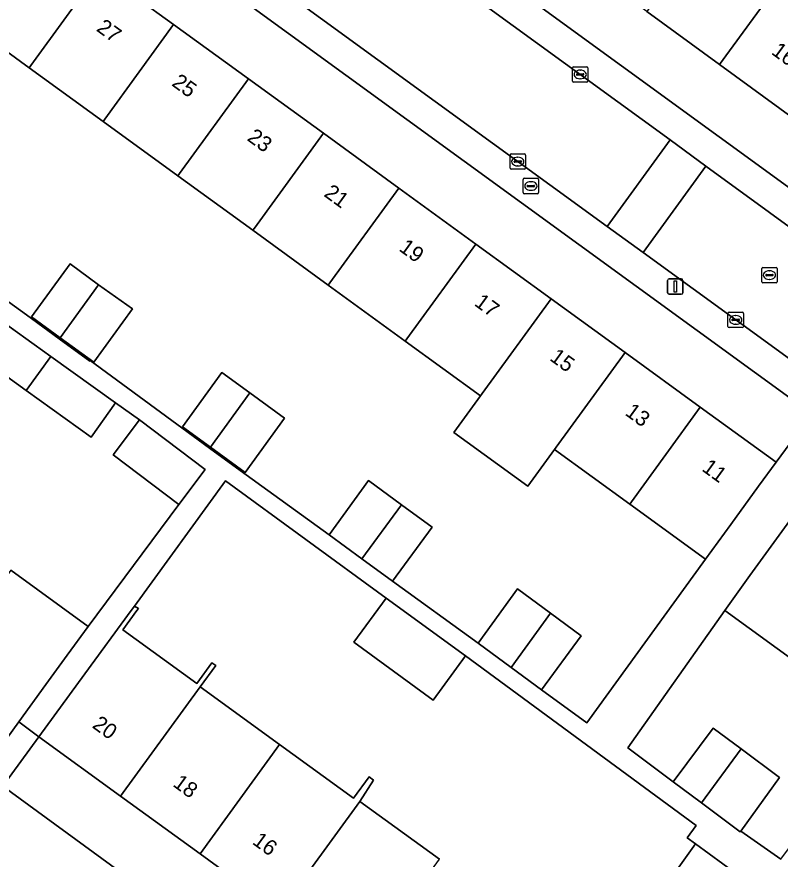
# Model space of a CAD drawing. Extents: x 159674 to 160531, y 382172 to 382904.
# Drawn here: x 160126.2 to 160175.7, y 382483.9 to 382538.5 of the extents above; entities that cross this region are included whole.
import ezdxf

# ---------------------------------------------------------------- set-up
doc = ezdxf.new("R2010")
doc.units = 0
for name, color, linetype in [('IMGEO_Brandkraan', 7, 'Continuous'), ('IMGEO_Erf', 7, 'Continuous'), ('IMGEO_Kolk', 7, 'Continuous'), ('IMGEO_Lichtmast', 7, 'Continuous'), ('IMGEO_Pand', 7, 'Continuous'), ('IMGEO_Pand_nummerreeks', 7, 'Continuous'), ('IMGEO_Rijbaan_lokaal_open', 7, 'Continuous'), ('IMGEO_Rioolput', 7, 'Continuous'), ('IMGEO_Voetpad_open', 7, 'Continuous')]:
    doc.layers.add(name, color=color, linetype=linetype)

msp = doc.modelspace()

# ---------------------------------------------------------------- linework, layer by layer
at = {"layer": 'IMGEO_Brandkraan'}
for p, q in [((160159.064, 382527.12), (160159.064, 382527.972)), ((160159.139, 382528.046), (160159.991, 382528.046)), ((160159.552, 382527.826), (160159.577, 382527.826)), ((160160.065, 382527.972), (160160.065, 382527.12)), ((160159.323, 382527.54), (160159.323, 382527.552)), ((160159.761, 382527.503), (160159.363, 382527.503)), ((160159.366, 382527.589), (160159.764, 382527.589)), ((160159.575, 382527.266), (160159.55, 382527.266)), ((160159.807, 382527.552), (160159.807, 382527.54)), ((160159.991, 382527.046), (160159.139, 382527.046))]:
    msp.add_line(p, q, dxfattribs=at)
for points in [[(160159.064, 382527.12), (160159.064, 382527.972)], [(160159.139, 382528.046), (160159.991, 382528.046)], [(160160.065, 382527.972), (160160.065, 382527.12)], [(160159.991, 382527.046), (160159.139, 382527.046)]]:
    msp.add_lwpolyline(points, dxfattribs=at)
for centre, radius, start, end in [((160159.141, 382527.97), 0.0765, 91.552, 178.448), ((160159.141, 382527.97), 0.0765, 91.552, 178.448), ((160159.989, 382527.97), 0.0765, 1.552, 88.448), ((160159.989, 382527.97), 0.0765, 1.552, 88.448), ((160159.363, 382527.549), 0.0403, 85.8775, 175.7526), ((160159.36, 382527.539), 0.0366, 178.938, 274.7102), ((160159.764, 382527.546), 0.043, 264.8664, 352.4533), ((160159.768, 382527.551), 0.0386, 1.7309, 96.639), ((160159.141, 382527.122), 0.0765, 181.552, 268.448), ((160159.141, 382527.122), 0.0765, 181.552, 268.448), ((160159.989, 382527.122), 0.0765, 271.552, 358.448), ((160159.989, 382527.122), 0.0765, 271.552, 358.448)]:
    msp.add_arc(centre, radius, start, end, dxfattribs=at)
for centre, major_axis, ratio, start_param, end_param in [((160159.551, 382527.546), (-0.387, 0.002), 0.722429, 4.712389, 7.853982), ((160159.576, 382527.546), (-0.39, 0.002), 0.717154, 1.570796, 4.712389)]:
    msp.add_ellipse(centre, major_axis=major_axis, ratio=ratio, start_param=start_param, end_param=end_param, dxfattribs=at)
at = {"layer": 'IMGEO_Erf'}
for points in [[(160127.897, 382562.669), (160184.209, 382521.695), (160184.808, 382522.535), (160186.417, 382524.795), (160181.637, 382528.275), (160176.758, 382531.828), (160171.799, 382535.439), (160167.082, 382538.873), (160162.337, 382542.328), (160157.384, 382545.934)], [(160117.459, 382553.168), (160116.806, 382552.256), (160121.807, 382548.622), (160126.656, 382545.098), (160131.584, 382541.517), (160136.387, 382538.026), (160141.237, 382534.502), (160146.105, 382530.965), (160150.991, 382527.414), (160155.991, 382523.78), (160160.872, 382520.234), (160165.672, 382516.745), (160170.553, 382513.198), (160175.469, 382509.626), (160177.234, 382512.001), (160177.794, 382512.755), (160121.273, 382553.859)], [(160121.293, 382523.187), (160126.833, 382519.19), (160128.969, 382517.622), (160130.945, 382516.172), (160130.979, 382516.218), (160136.587, 382512.101), (160138.724, 382510.532), (160140.699, 382509.083), (160146.468, 382504.92), (160149.018, 382508.437), (160151.159, 382506.866), (160153.151, 382505.404), (160150.58, 382501.902), (160156.148, 382497.884), (160158.698, 382501.401), (160160.839, 382499.83), (160162.831, 382498.368), (160160.26, 382494.866), (160163.181, 382492.722), (160170.895, 382503.333), (160165.979, 382506.906), (160161.098, 382510.453), (160159.362, 382508.064), (160154.564, 382511.551), (160156.297, 382513.941), (160151.417, 382517.488), (160146.418, 382521.12), (160141.531, 382524.672), (160136.663, 382528.21), (160131.814, 382531.734), (160127.01, 382535.224), (160122.082, 382538.806)], [(160125.823, 382502.62), (160130.845, 382498.975), (160136.723, 382506.88), (160132.467, 382510.102), (160134.182, 382512.366), (160132.611, 382513.47), (160131.029, 382511.262), (160126.818, 382514.281), (160123.027, 382517)], [(160167.97, 382481.681), (160170.234, 382484.868), (160169.698, 382485.261), (160170.274, 382486.048), (160155.319, 382497.055), (160153.231, 382494.194), (160148.078, 382497.954), (160150.166, 382500.815), (160139.754, 382508.413), (160133.844, 382500.294), (160134.105, 382500.145), (160133.999, 382500), (160133.09, 382498.758), (160137.889, 382495.27), (160138.869, 382496.618), (160139.115, 382496.439), (160138.113, 382495.063), (160143.265, 382491.318), (160148.063, 382487.832), (160149.063, 382489.208), (160149.354, 382488.996), (160148.464, 382487.621), (160153.625, 382483.87)], [(160182.094, 382492.77), (160177.116, 382496.389), (160172.149, 382500), (160165.851, 382491.086), (160168.791, 382488.896), (160171.386, 382492.38), (160173.197, 382491.031), (160175.695, 382489.17), (160173.177, 382485.697), (160175.768, 382483.874), (160179.323, 382488.647), (160182.164, 382486.531), (160181.035, 382485.016), (160182.848, 382483.665), (160184.767, 382482.236), (160182.34, 382478.979), (160182.963, 382478.515), (160185.543, 382476.768), (160187.968, 382480.105), (160192.854, 382476.554), (160193.609, 382475.995), (160197.153, 382480.914)]]:
    msp.add_lwpolyline(points, dxfattribs=at)
for points in [[(160129.028, 382517.703), (160127.167, 382519.053), (160129.666, 382522.499), (160131.523, 382521.136), (160133.71, 382519.567), (160131.211, 382516.121)], [(160141.333, 382514.123), (160143.589, 382512.486), (160141.037, 382508.966), (160138.776, 382510.604), (160136.952, 382511.927), (160139.505, 382515.448)], [(160143.26, 382480.459), (160138.099, 382484.21), (160132.938, 382487.961), (160127.653, 382491.801), (160125.316, 382488.609), (160161.358, 382462.265), (160161.521, 382462.147), (160163.916, 382465.448), (160163.756, 382465.564), (160158.743, 382469.207), (160153.582, 382472.958), (160148.42, 382476.709)]]:
    msp.add_lwpolyline(points, close=True, dxfattribs=at)
at = {"layer": 'IMGEO_Kolk'}
for p, q in [((160162.26, 382534.357), (160162.26, 382535.209)), ((160162.335, 382535.283), (160163.187, 382535.283)), ((160162.748, 382535.063), (160162.773, 382535.063)), ((160163.261, 382535.209), (160163.261, 382534.357)), ((160162.519, 382534.777), (160162.519, 382534.789)), ((160162.957, 382534.74), (160162.559, 382534.74)), ((160162.562, 382534.826), (160162.96, 382534.826)), ((160162.771, 382534.503), (160162.746, 382534.503)), ((160163.003, 382534.789), (160163.003, 382534.777)), ((160163.187, 382534.283), (160162.335, 382534.283)), ((160158.211, 382528.704), (160158.211, 382529.556)), ((160158.286, 382529.63), (160159.138, 382529.63)), ((160158.699, 382529.41), (160158.724, 382529.41)), ((160159.212, 382529.556), (160159.212, 382528.704)), ((160158.47, 382529.124), (160158.47, 382529.136)), ((160158.908, 382529.087), (160158.51, 382529.087)), ((160158.513, 382529.173), (160158.911, 382529.173)), ((160158.722, 382528.85), (160158.697, 382528.85)), ((160158.954, 382529.136), (160158.954, 382529.124)), ((160159.138, 382528.63), (160158.286, 382528.63)), ((160172.347, 382518.432), (160172.347, 382519.284)), ((160172.422, 382519.358), (160173.274, 382519.358)), ((160172.835, 382519.138), (160172.86, 382519.138)), ((160173.348, 382519.284), (160173.348, 382518.432)), ((160172.606, 382518.852), (160172.606, 382518.864)), ((160173.044, 382518.815), (160172.646, 382518.815)), ((160172.649, 382518.901), (160173.047, 382518.901)), ((160172.858, 382518.578), (160172.833, 382518.578)), ((160173.09, 382518.864), (160173.09, 382518.852)), ((160173.274, 382518.358), (160172.422, 382518.358))]:
    msp.add_line(p, q, dxfattribs=at)
for points in [[(160162.26, 382534.357), (160162.26, 382535.209)], [(160162.335, 382535.283), (160163.187, 382535.283)], [(160163.261, 382535.209), (160163.261, 382534.357)], [(160163.187, 382534.283), (160162.335, 382534.283)], [(160158.211, 382528.704), (160158.211, 382529.556)], [(160158.286, 382529.63), (160159.138, 382529.63)], [(160159.212, 382529.556), (160159.212, 382528.704)], [(160159.138, 382528.63), (160158.286, 382528.63)], [(160172.347, 382518.432), (160172.347, 382519.284)], [(160172.422, 382519.358), (160173.274, 382519.358)], [(160173.348, 382519.284), (160173.348, 382518.432)], [(160173.274, 382518.358), (160172.422, 382518.358)]]:
    msp.add_lwpolyline(points, dxfattribs=at)
for centre, radius, start, end in [((160162.337, 382535.207), 0.0765, 91.552, 178.448), ((160162.337, 382535.207), 0.0765, 91.552, 178.448), ((160163.185, 382535.207), 0.0765, 1.552, 88.448), ((160163.185, 382535.207), 0.0765, 1.552, 88.448), ((160162.337, 382534.359), 0.0765, 181.552, 268.448), ((160162.337, 382534.359), 0.0765, 181.552, 268.448), ((160162.559, 382534.786), 0.0403, 85.8775, 175.7526), ((160162.556, 382534.776), 0.0366, 178.938, 274.7102), ((160162.96, 382534.783), 0.043, 264.8664, 352.4533), ((160162.964, 382534.788), 0.0386, 1.7309, 96.639), ((160163.185, 382534.359), 0.0765, 271.552, 358.448), ((160163.185, 382534.359), 0.0765, 271.552, 358.448), ((160158.288, 382529.554), 0.0765, 91.552, 178.448), ((160158.288, 382529.554), 0.0765, 91.552, 178.448), ((160159.136, 382529.554), 0.0765, 1.552, 88.448), ((160159.136, 382529.554), 0.0765, 1.552, 88.448), ((160158.51, 382529.133), 0.0403, 85.8775, 175.7526), ((160158.507, 382529.123), 0.0366, 178.938, 274.7102), ((160158.911, 382529.13), 0.043, 264.8664, 352.4533), ((160158.915, 382529.135), 0.0386, 1.7309, 96.639), ((160158.288, 382528.706), 0.0765, 181.552, 268.448), ((160158.288, 382528.706), 0.0765, 181.552, 268.448), ((160159.136, 382528.706), 0.0765, 271.552, 358.448), ((160159.136, 382528.706), 0.0765, 271.552, 358.448), ((160172.424, 382519.282), 0.0765, 91.552, 178.448), ((160172.424, 382519.282), 0.0765, 91.552, 178.448), ((160173.272, 382519.282), 0.0765, 1.552, 88.448), ((160173.272, 382519.282), 0.0765, 1.552, 88.448), ((160172.646, 382518.861), 0.0403, 85.8775, 175.7526), ((160172.643, 382518.851), 0.0366, 178.938, 274.7102), ((160173.047, 382518.858), 0.043, 264.8664, 352.4533), ((160173.051, 382518.863), 0.0386, 1.7309, 96.639), ((160172.424, 382518.434), 0.0765, 181.552, 268.448), ((160172.424, 382518.434), 0.0765, 181.552, 268.448), ((160173.272, 382518.434), 0.0765, 271.552, 358.448), ((160173.272, 382518.434), 0.0765, 271.552, 358.448)]:
    msp.add_arc(centre, radius, start, end, dxfattribs=at)
for centre, major_axis, ratio, start_param, end_param in [((160162.747, 382534.783), (-0.387, 0.002), 0.722429, 4.712389, 7.853982), ((160162.772, 382534.783), (-0.39, 0.002), 0.717154, 1.570796, 4.712389), ((160158.698, 382529.13), (-0.387, 0.002), 0.722429, 4.712389, 7.853982), ((160158.723, 382529.13), (-0.39, 0.002), 0.717154, 1.570796, 4.712389), ((160172.834, 382518.858), (-0.387, 0.002), 0.722429, 4.712389, 7.853982), ((160172.859, 382518.858), (-0.39, 0.002), 0.717154, 1.570796, 4.712389)]:
    msp.add_ellipse(centre, major_axis=major_axis, ratio=ratio, start_param=start_param, end_param=end_param, dxfattribs=at)
at = {"layer": 'IMGEO_Lichtmast'}
for p, q in [((160168.429, 382520.624), (160168.429, 382521.424)), ((160168.429, 382521.424), (160168.429, 382520.624)), ((160168.529, 382521.524), (160169.319, 382521.524)), ((160169.319, 382521.524), (160168.529, 382521.524)), ((160169.419, 382521.424), (160169.419, 382520.624)), ((160169.419, 382520.624), (160169.419, 382521.424)), ((160169.319, 382520.524), (160168.529, 382520.524)), ((160168.529, 382520.524), (160169.319, 382520.524))]:
    msp.add_line(p, q, dxfattribs=at)
msp.add_lwpolyline([(160168.849, 382521.399), (160168.999, 382521.399), (160168.999, 382520.649), (160168.849, 382520.649), (160168.849, 382521.399)], dxfattribs=at)
for centre, start, end in [((160168.529, 382521.424), 90, 180), ((160168.529, 382521.424), 90, 180), ((160169.319, 382521.424), 0, 90), ((160169.319, 382521.424), 360, 90), ((160168.529, 382520.624), 180, 270), ((160168.529, 382520.624), 180, 270), ((160169.319, 382520.624), 270, 0), ((160169.319, 382520.624), 270, 0)]:
    msp.add_arc(centre, 0.1, start, end, dxfattribs=at)
at = {"layer": 'IMGEO_Pand'}
for points in [[(160122.082, 382538.806), (160127.01, 382535.224), (160127.119, 382535.372), (160131.584, 382541.517), (160126.656, 382545.098), (160122.19, 382538.954)], [(160167.082, 382538.873), (160171.799, 382535.439), (160176.396, 382541.751), (160171.679, 382545.186)], [(160131.584, 382541.517), (160127.119, 382535.372), (160127.01, 382535.224), (160131.814, 382531.734), (160131.922, 382531.882), (160136.387, 382538.026)], [(160181.355, 382538.141), (160176.396, 382541.751), (160171.799, 382535.439), (160176.758, 382531.828)], [(160136.663, 382528.21), (160136.771, 382528.357), (160141.237, 382534.502), (160136.387, 382538.026), (160131.922, 382531.882), (160131.814, 382531.734)], [(160136.663, 382528.21), (160141.531, 382524.672), (160141.639, 382524.819), (160146.105, 382530.965), (160141.237, 382534.502), (160136.771, 382528.357)], [(160146.418, 382521.12), (160146.525, 382521.268), (160150.991, 382527.414), (160146.105, 382530.965), (160141.639, 382524.819), (160141.531, 382524.672)], [(160146.418, 382521.12), (160151.417, 382517.488), (160151.525, 382517.634), (160155.991, 382523.78), (160150.991, 382527.414), (160146.525, 382521.268)], [(160151.417, 382517.488), (160156.297, 382513.941), (160156.406, 382514.087), (160160.872, 382520.234), (160155.991, 382523.78), (160151.525, 382517.634)], [(160131.523, 382521.136), (160129.666, 382522.499), (160127.167, 382519.053), (160129.028, 382517.703)], [(160131.523, 382521.136), (160129.028, 382517.703), (160131.211, 382516.121), (160133.71, 382519.567)], [(160165.672, 382516.745), (160160.872, 382520.234), (160156.406, 382514.087), (160156.297, 382513.941), (160154.564, 382511.551), (160159.362, 382508.064), (160161.098, 382510.453), (160161.205, 382510.598)], [(160126.818, 382514.281), (160128.414, 382516.479), (160124.609, 382519.207), (160123.027, 382517)], [(160126.818, 382514.281), (160131.029, 382511.262), (160132.611, 382513.47), (160128.414, 382516.479)], [(160170.553, 382513.198), (160165.672, 382516.745), (160161.205, 382510.598), (160161.098, 382510.453), (160165.979, 382506.906), (160166.086, 382507.051)], [(160141.333, 382514.123), (160139.505, 382515.448), (160136.952, 382511.927), (160138.776, 382510.604)], [(160141.333, 382514.123), (160138.776, 382510.604), (160141.037, 382508.966), (160143.589, 382512.486)], [(160170.553, 382513.198), (160166.086, 382507.051), (160165.979, 382506.906), (160170.895, 382503.333), (160172.53, 382505.582), (160174.336, 382508.068), (160175.469, 382509.626)], [(160134.182, 382512.366), (160132.467, 382510.102), (160136.723, 382506.88), (160138.437, 382509.144)], [(160148.606, 382503.351), (160151.159, 382506.866), (160149.018, 382508.437), (160146.468, 382504.92)], [(160148.606, 382503.351), (160150.58, 382501.902), (160153.151, 382505.404), (160151.159, 382506.866)], [(160177.116, 382496.389), (160179.757, 382500), (160181.704, 382502.662), (160176.698, 382506.323), (160173.759, 382502.279), (160172.149, 382500)], [(160129.485, 382497.104), (160130.845, 382498.975), (160125.823, 382502.62), (160124.463, 382500.746), (160123.92, 382500), (160120.154, 382494.811), (160125.171, 382491.169), (160126.342, 382492.78), (160128.102, 382495.201)], [(160160.839, 382499.83), (160158.698, 382501.401), (160156.148, 382497.884), (160158.285, 382496.316)], [(160150.166, 382500.815), (160148.078, 382497.954), (160153.231, 382494.194), (160155.319, 382497.055)], [(160138.113, 382495.063), (160139.115, 382496.439), (160138.869, 382496.618), (160137.889, 382495.27), (160133.09, 382498.758), (160133.999, 382500), (160134.105, 382500.145), (160133.844, 382500.294), (160133.63, 382500), (160130.637, 382495.894), (160127.653, 382491.801), (160132.938, 382487.961)], [(160160.839, 382499.83), (160158.285, 382496.316), (160160.26, 382494.866), (160162.831, 382498.368)], [(160143.265, 382491.318), (160138.113, 382495.063), (160132.938, 382487.961), (160138.099, 382484.21)], [(160173.197, 382491.031), (160171.386, 382492.38), (160168.791, 382488.896), (160170.633, 382487.524)], [(160138.099, 382484.21), (160143.26, 382480.459), (160148.464, 382487.621), (160149.354, 382488.996), (160149.063, 382489.208), (160148.063, 382487.832), (160143.265, 382491.318)], [(160175.695, 382489.17), (160173.197, 382491.031), (160170.633, 382487.524), (160173.145, 382485.653), (160173.177, 382485.697)], [(160148.42, 382476.709), (160153.625, 382483.87), (160148.464, 382487.621), (160143.26, 382480.459)], [(160170.234, 382484.868), (160167.97, 382481.681), (160172.364, 382478.461), (160172.878, 382479.162), (160174.675, 382481.615)]]:
    msp.add_lwpolyline(points, close=True, dxfattribs=at)
at = {"layer": 'IMGEO_Rijbaan_lokaal_open'}
for points in [[(160164.514, 382524.914), (160168.596, 382530.532), (160153.206, 382541.739), (160123.485, 382563.377), (160120.554, 382565.511), (160112.814, 382571.146), (160108.691, 382565.482)], [(160164.514, 382524.914), (160166.836, 382523.227), (160170.916, 382528.842), (160168.596, 382530.532)]]:
    msp.add_lwpolyline(points, close=True, dxfattribs=at)
for points in [[(160170.916, 382528.842), (160166.836, 382523.227), (160198.798, 382500), (160204.282, 382495.961)], [(160207.614, 382502.119), (160170.916, 382528.842)]]:
    msp.add_lwpolyline(points, dxfattribs=at)
at = {"layer": 'IMGEO_Rioolput'}
for p, q in [((160174.537, 382521.339), (160174.537, 382522.191)), ((160174.612, 382522.265), (160175.464, 382522.265)), ((160174.796, 382521.759), (160174.796, 382521.771)), ((160174.839, 382521.808), (160175.237, 382521.808)), ((160175.025, 382522.045), (160175.05, 382522.045)), ((160175.28, 382521.771), (160175.28, 382521.759)), ((160175.538, 382522.191), (160175.538, 382521.339)), ((160175.464, 382521.265), (160174.612, 382521.265)), ((160175.234, 382521.722), (160174.836, 382521.722)), ((160175.048, 382521.485), (160175.023, 382521.485))]:
    msp.add_line(p, q, dxfattribs=at)
for points in [[(160174.537, 382521.339), (160174.537, 382522.191)], [(160174.612, 382522.265), (160175.464, 382522.265)], [(160175.538, 382522.191), (160175.538, 382521.339)], [(160175.464, 382521.265), (160174.612, 382521.265)]]:
    msp.add_lwpolyline(points, dxfattribs=at)
for centre, radius, start, end in [((160174.614, 382522.189), 0.0765, 91.552, 178.448), ((160174.614, 382522.189), 0.0765, 91.552, 178.448), ((160174.836, 382521.768), 0.0403, 85.8775, 175.7526), ((160174.833, 382521.758), 0.0366, 178.938, 274.7102), ((160175.237, 382521.765), 0.043, 264.8664, 352.4533), ((160175.241, 382521.77), 0.0386, 1.7309, 96.639), ((160175.462, 382522.189), 0.0765, 1.552, 88.448), ((160175.462, 382522.189), 0.0765, 1.552, 88.448), ((160174.614, 382521.341), 0.0765, 181.552, 268.448), ((160174.614, 382521.341), 0.0765, 181.552, 268.448), ((160175.462, 382521.341), 0.0765, 271.552, 358.448), ((160175.462, 382521.341), 0.0765, 271.552, 358.448)]:
    msp.add_arc(centre, radius, start, end, dxfattribs=at)
for centre, major_axis, ratio, start_param, end_param in [((160175.024, 382521.765), (-0.387, 0.002), 0.722429, 4.712389, 7.853982), ((160175.049, 382521.765), (-0.39, 0.002), 0.717154, 1.570796, 4.712389)]:
    msp.add_ellipse(centre, major_axis=major_axis, ratio=ratio, start_param=start_param, end_param=end_param, dxfattribs=at)
at = {"layer": 'IMGEO_Voetpad_open'}
for points in [[(160103.182, 382578.158), (160110.485, 382572.841), (160112.814, 382571.146), (160120.554, 382565.511), (160121.166, 382566.352), (160124.097, 382564.218), (160123.485, 382563.377), (160153.206, 382541.739), (160168.596, 382530.532), (160170.916, 382528.842), (160207.614, 382502.119)], [(160166.836, 382523.227), (160164.514, 382524.914), (160108.691, 382565.482), (160106.361, 382567.175), (160098.735, 382572.717)], [(160210.164, 382504.096), (160187.205, 382520.79), (160184.808, 382522.535), (160184.209, 382521.695), (160127.897, 382562.669)], [(160121.273, 382553.859), (160177.794, 382512.755), (160177.234, 382512.001), (160179.581, 382510.186), (160193.511, 382500), (160201.923, 382493.849)], [(160177.234, 382512.001), (160175.469, 382509.626), (160174.336, 382508.068), (160172.53, 382505.582), (160170.895, 382503.333), (160163.181, 382492.722), (160160.26, 382494.866), (160158.285, 382496.316), (160156.148, 382497.884), (160150.58, 382501.902), (160148.606, 382503.351), (160146.468, 382504.92), (160140.699, 382509.083), (160138.724, 382510.532), (160136.587, 382512.101), (160130.979, 382516.218), (160130.945, 382516.172), (160128.969, 382517.622), (160126.833, 382519.19), (160121.293, 382523.187)], [(160204.282, 382495.961), (160198.798, 382500), (160166.836, 382523.227)], [(160124.609, 382519.207), (160128.414, 382516.479), (160132.611, 382513.47), (160134.182, 382512.366), (160138.437, 382509.144), (160136.723, 382506.88), (160130.845, 382498.975), (160129.485, 382497.104), (160128.102, 382495.201), (160126.342, 382492.78), (160127.653, 382491.801), (160130.637, 382495.894), (160133.63, 382500), (160133.844, 382500.294), (160139.754, 382508.413), (160150.166, 382500.815), (160155.319, 382497.055), (160170.274, 382486.048), (160169.698, 382485.261), (160170.234, 382484.868), (160174.675, 382481.615)], [(160174.179, 382449.327), (160174.199, 382452.933), (160173.407, 382451.842), (160162.122, 382460.043), (160162.914, 382461.134), (160161.521, 382462.147), (160161.358, 382462.265), (160125.316, 382488.609), (160127.653, 382491.801), (160126.342, 382492.78), (160125.171, 382491.169), (160124.011, 382489.563), (160122.995, 382488.155), (160106.723, 382500), (160088.55, 382513.229)], [(160175.768, 382483.874), (160173.177, 382485.697), (160173.145, 382485.653), (160170.633, 382487.524), (160168.791, 382488.896), (160165.851, 382491.086), (160172.149, 382500), (160173.759, 382502.279), (160176.698, 382506.323)]]:
    msp.add_lwpolyline(points, dxfattribs=at)

# ---------------------------------------------------------------- texts
at = {"layer": 'IMGEO_Pand_nummerreeks'}
for s, rotation, p in [('27', 323.9944, (160131.319, 382537.654)), ('16', 323.9409, (160175.105, 382536.148)), ('25', 323.9944, (160136.208, 382534.102)), ('23', 323.9944, (160141.096, 382530.549)), ('21', 323.9944, (160146.076, 382526.931)), ('19', 323.9944, (160150.947, 382523.39)), ('17', 323.9944, (160155.835, 382519.838)), ('15', 323.9953, (160160.724, 382516.285)), ('13', 323.9944, (160165.612, 382512.733)), ('11', 323.9944, (160170.594, 382509.113)), ('20', 323.9953, (160131.047, 382492.449)), ('18', 323.9953, (160136.278, 382488.648)), ('16', 323.9931, (160141.433, 382484.902))]:
    msp.add_text(s, height=1, rotation=rotation, dxfattribs=at).set_placement(p)

doc.saveas('drawing.dxf')
